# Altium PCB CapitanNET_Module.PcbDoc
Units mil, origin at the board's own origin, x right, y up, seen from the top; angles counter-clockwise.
Board outline not stored, 4 copper layers (Top Layer, Mid-Layer 1, Mid-Layer 2, Bottom Layer); 12 components, 0 nets, 301 pads, 51 vias.
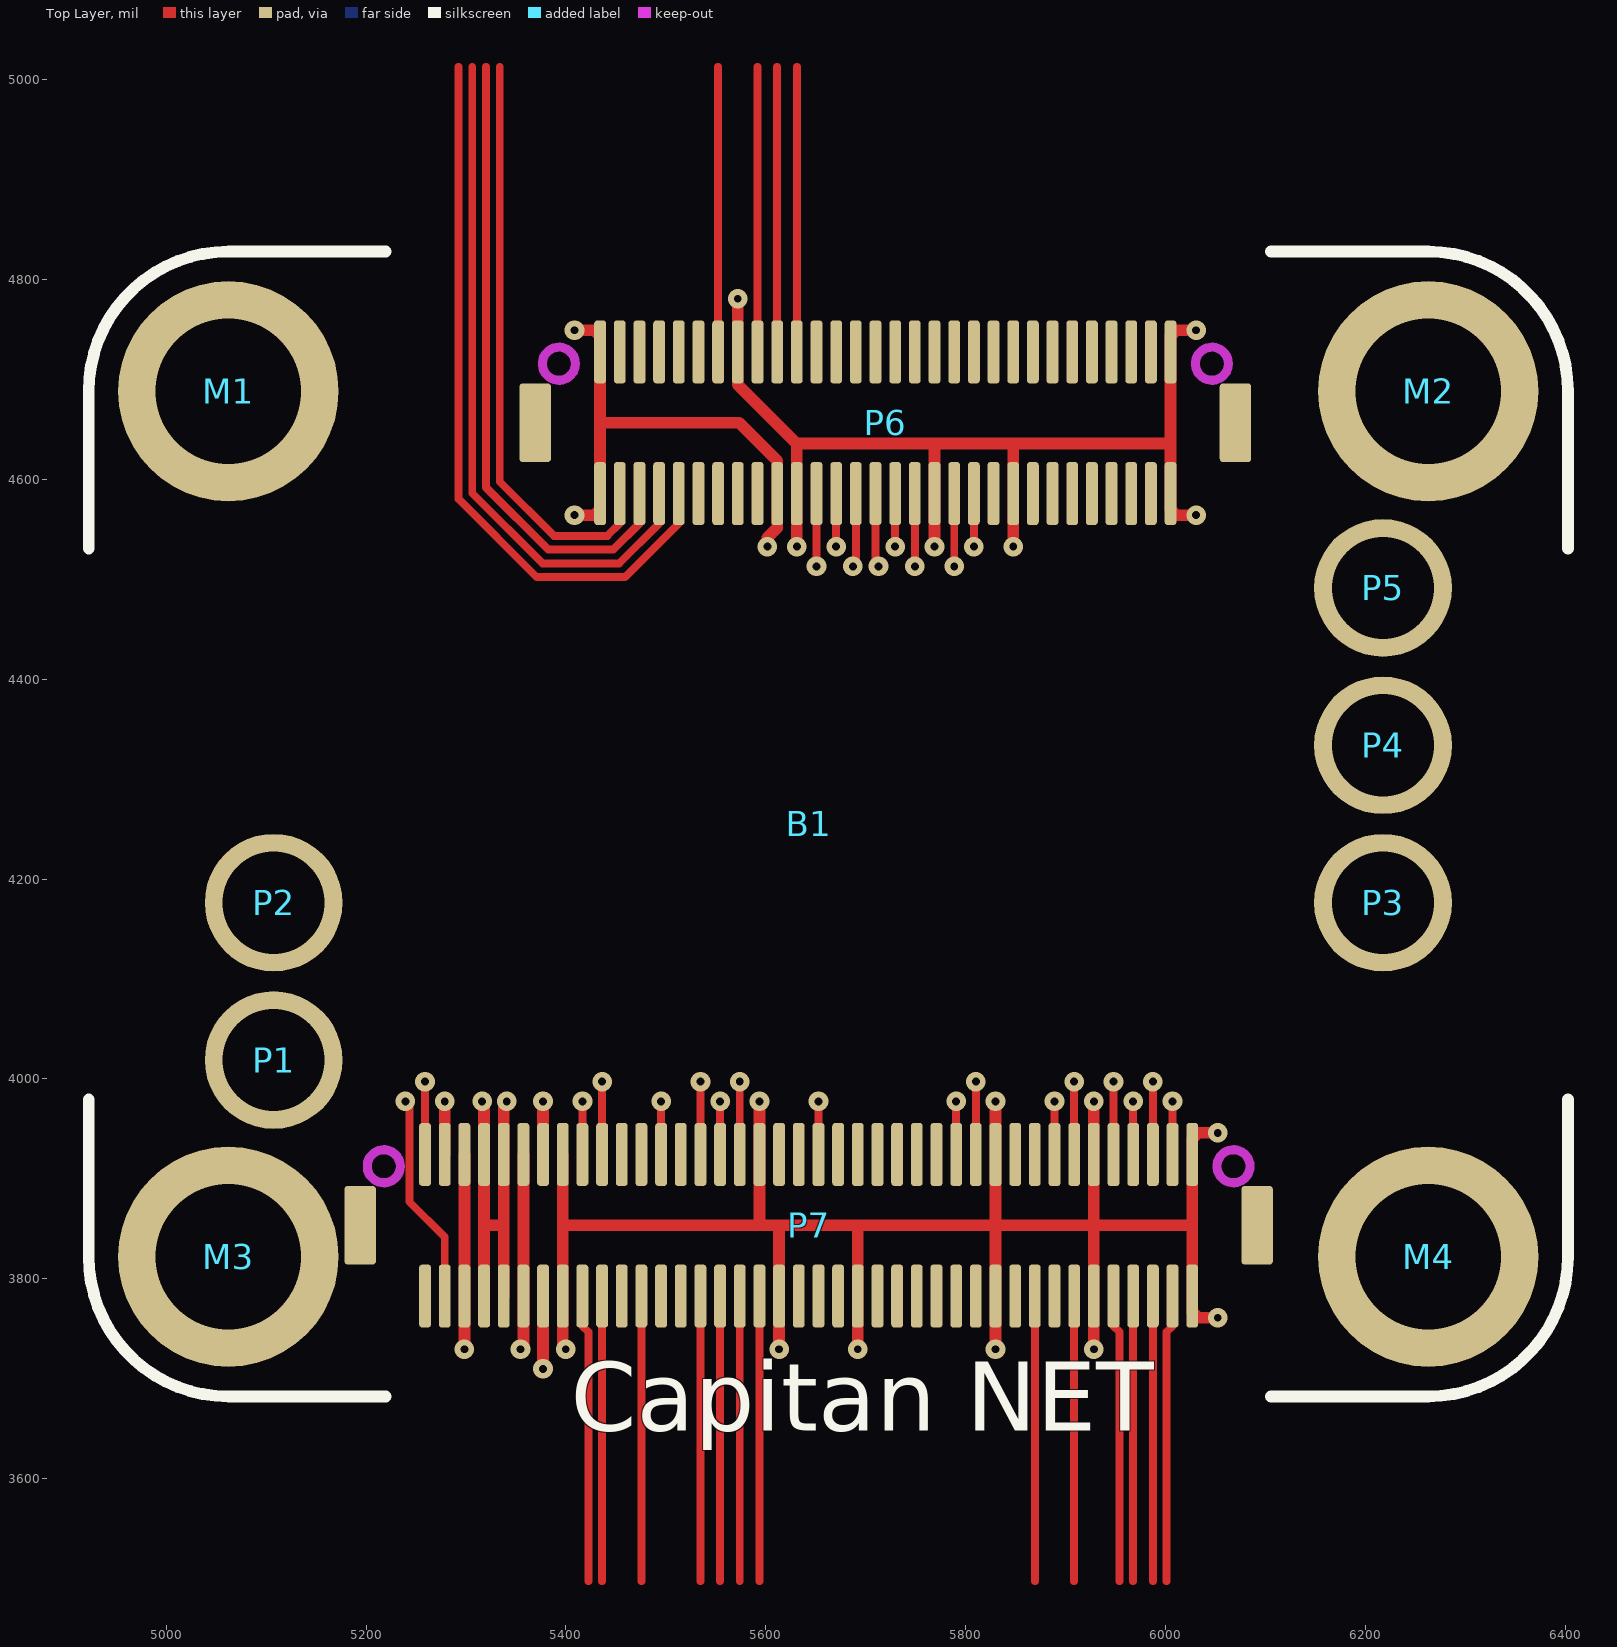
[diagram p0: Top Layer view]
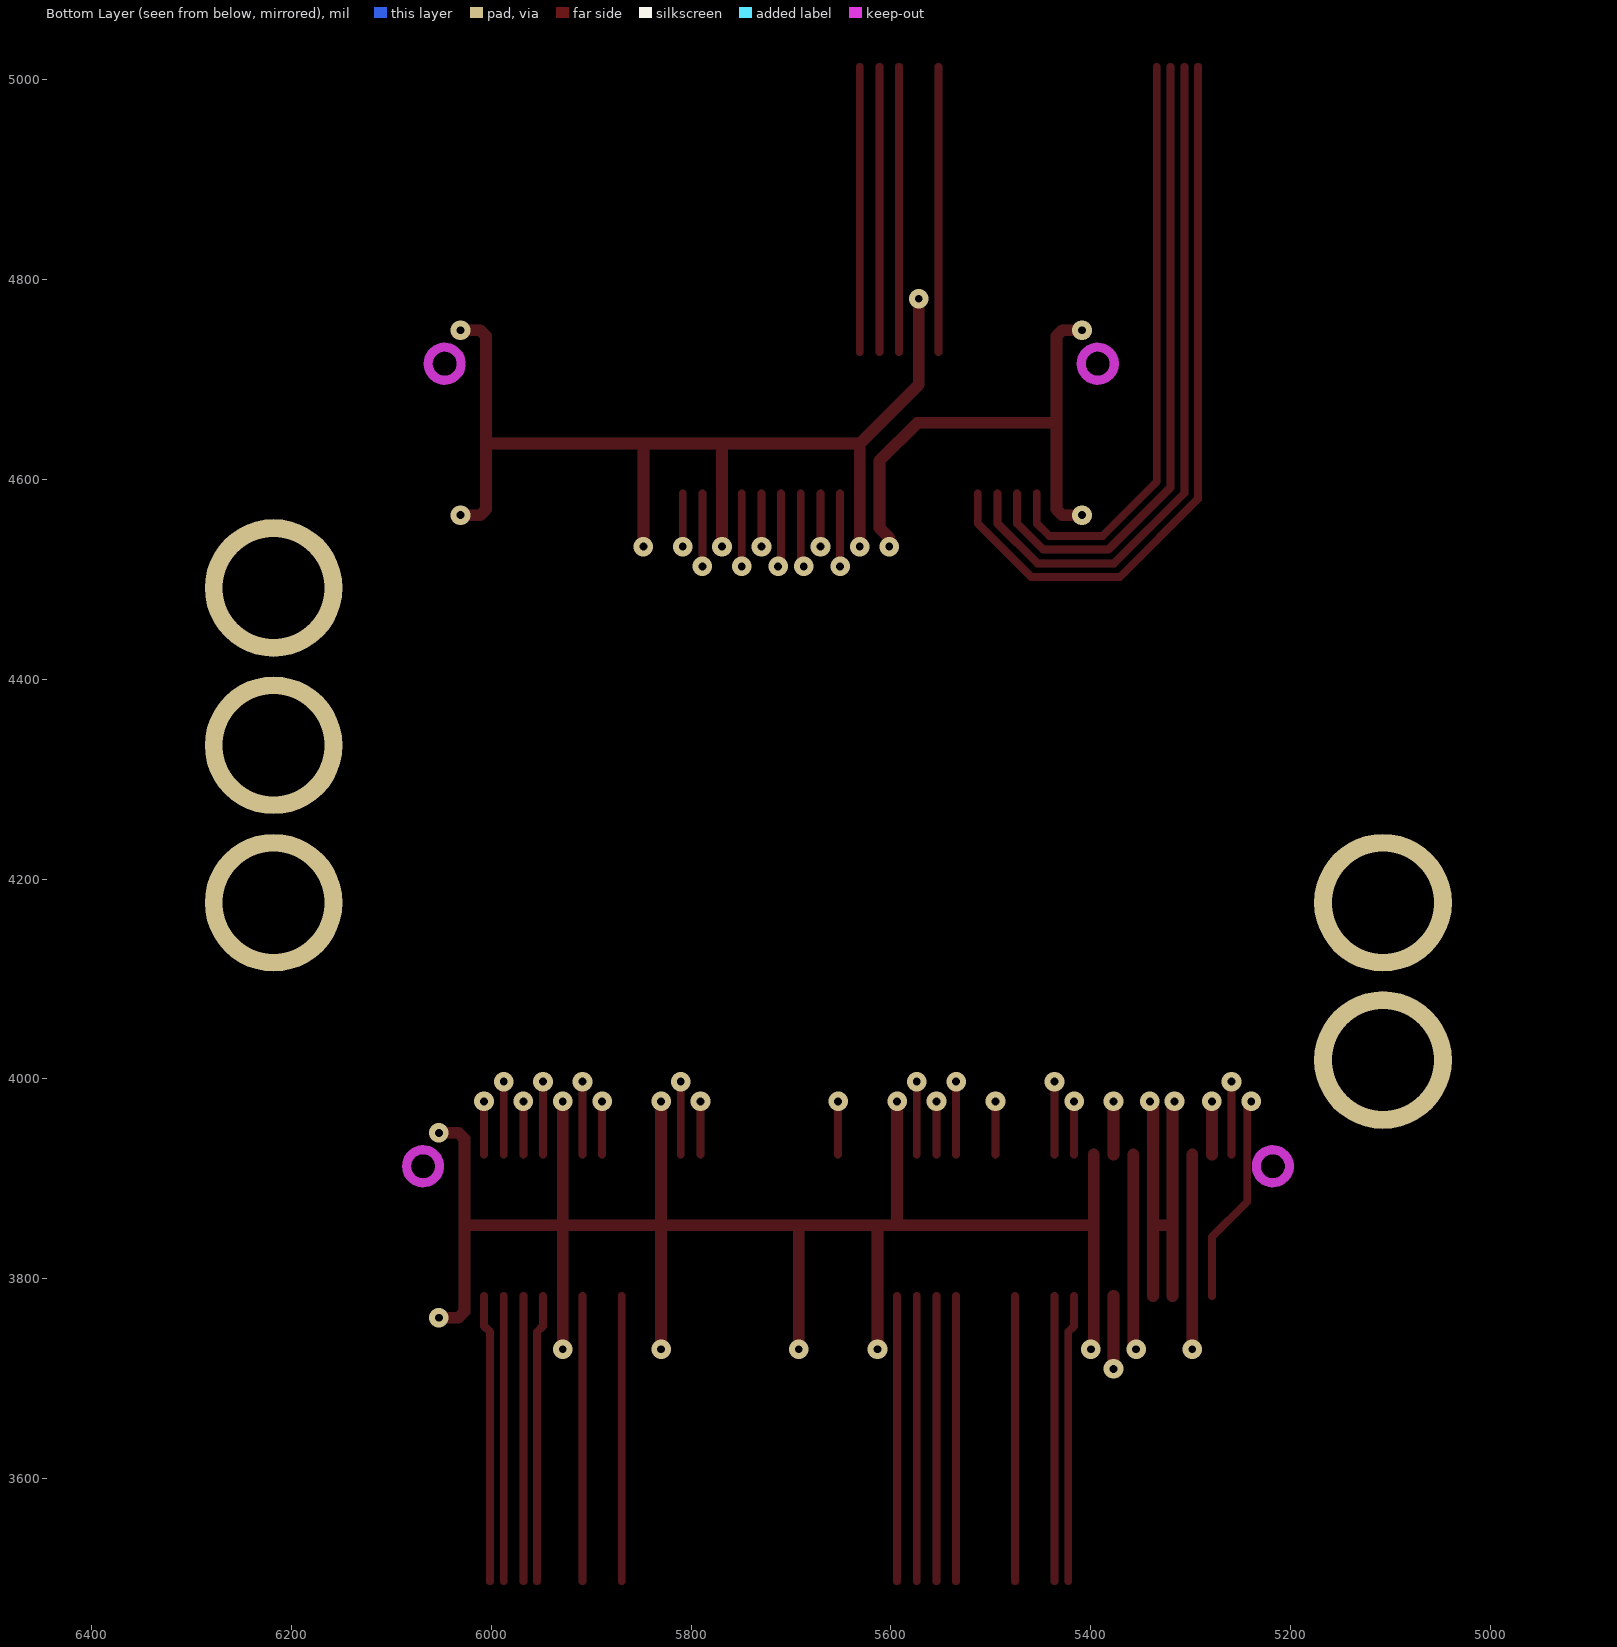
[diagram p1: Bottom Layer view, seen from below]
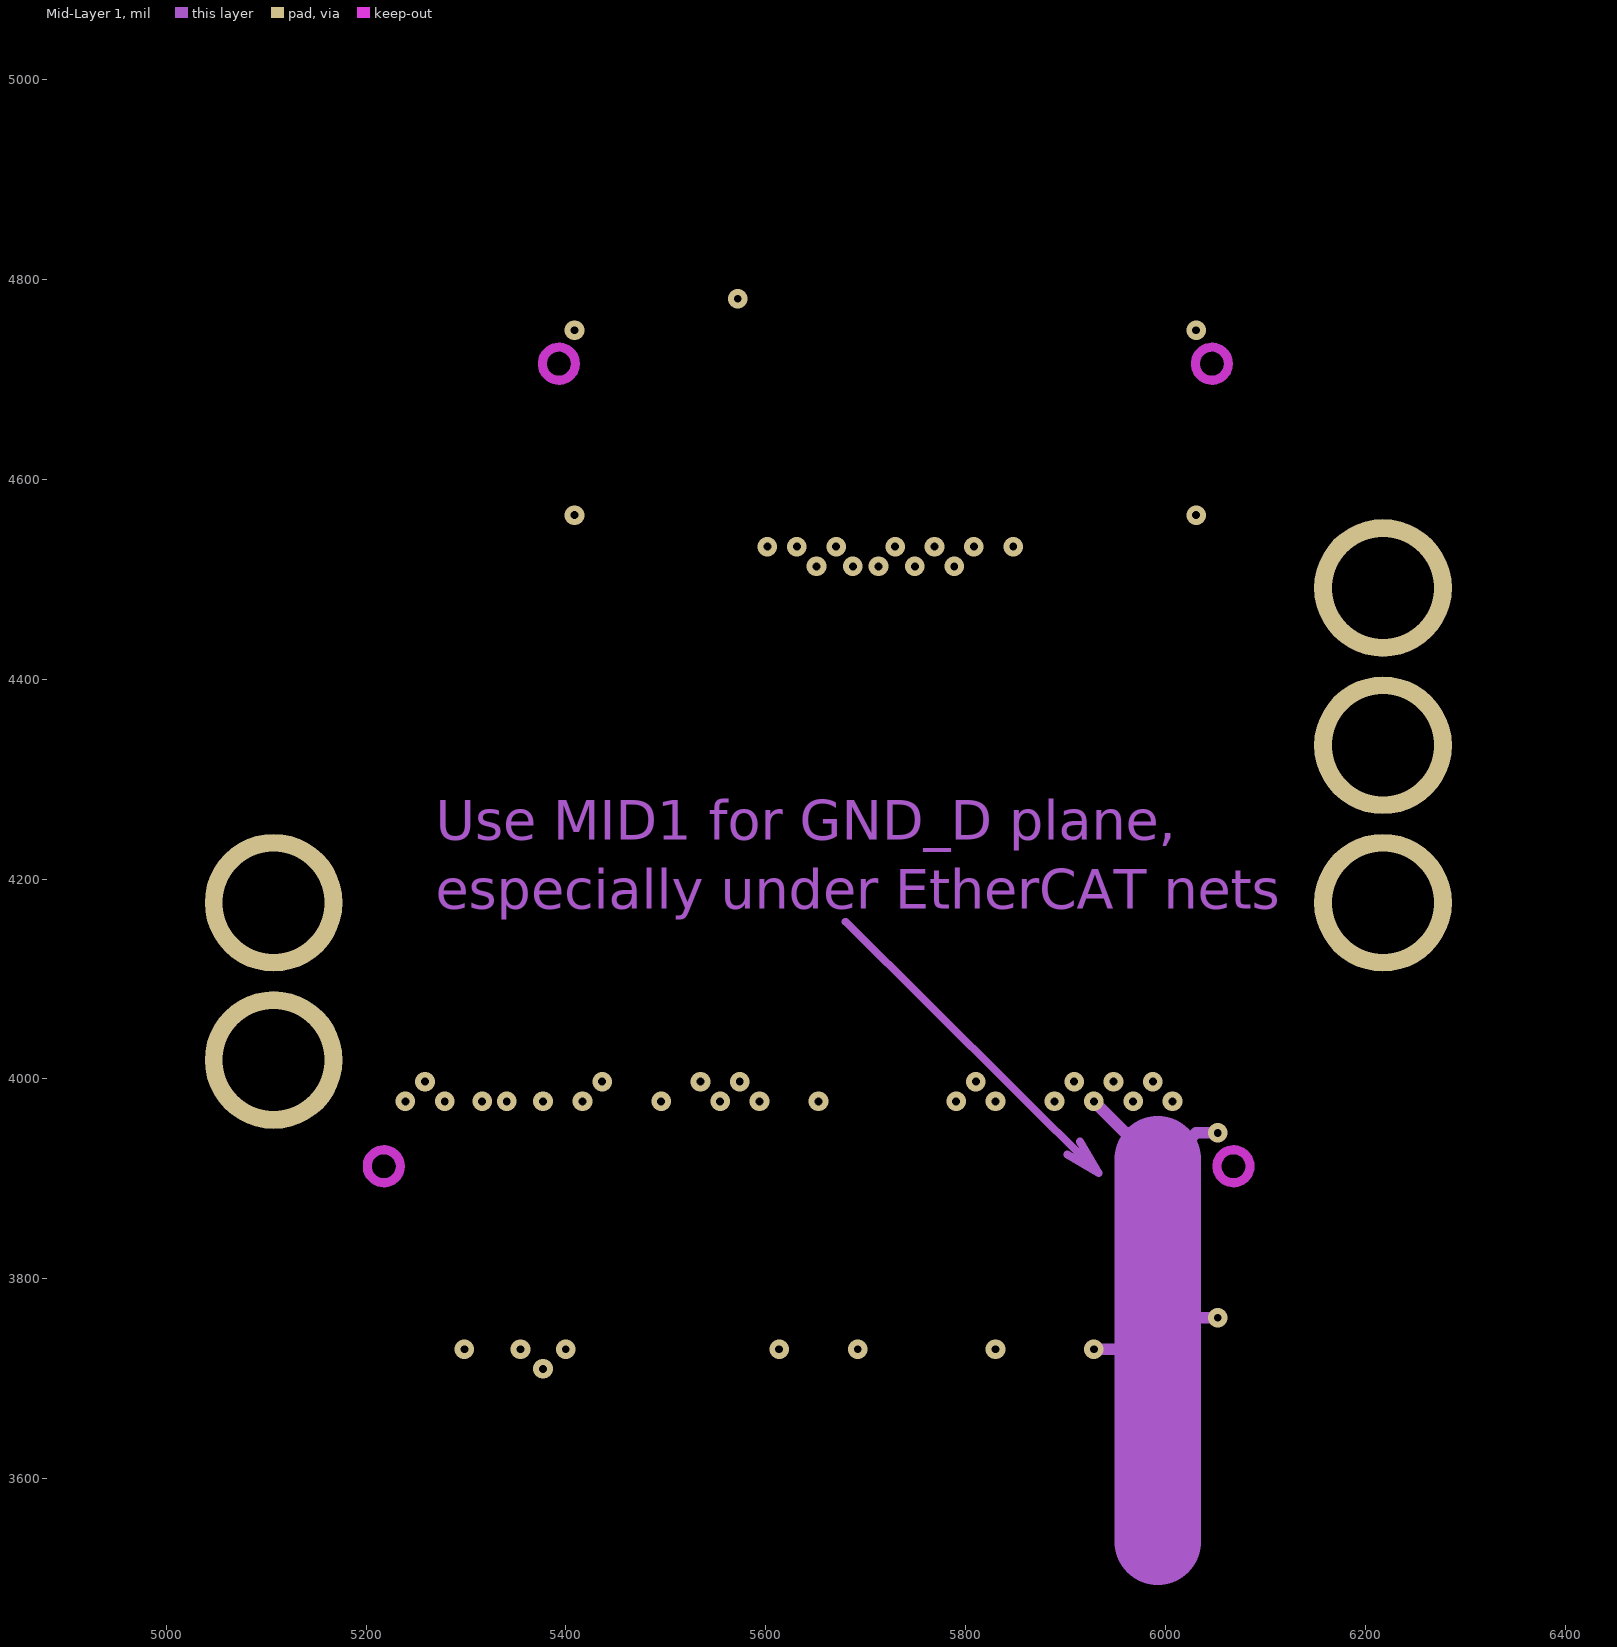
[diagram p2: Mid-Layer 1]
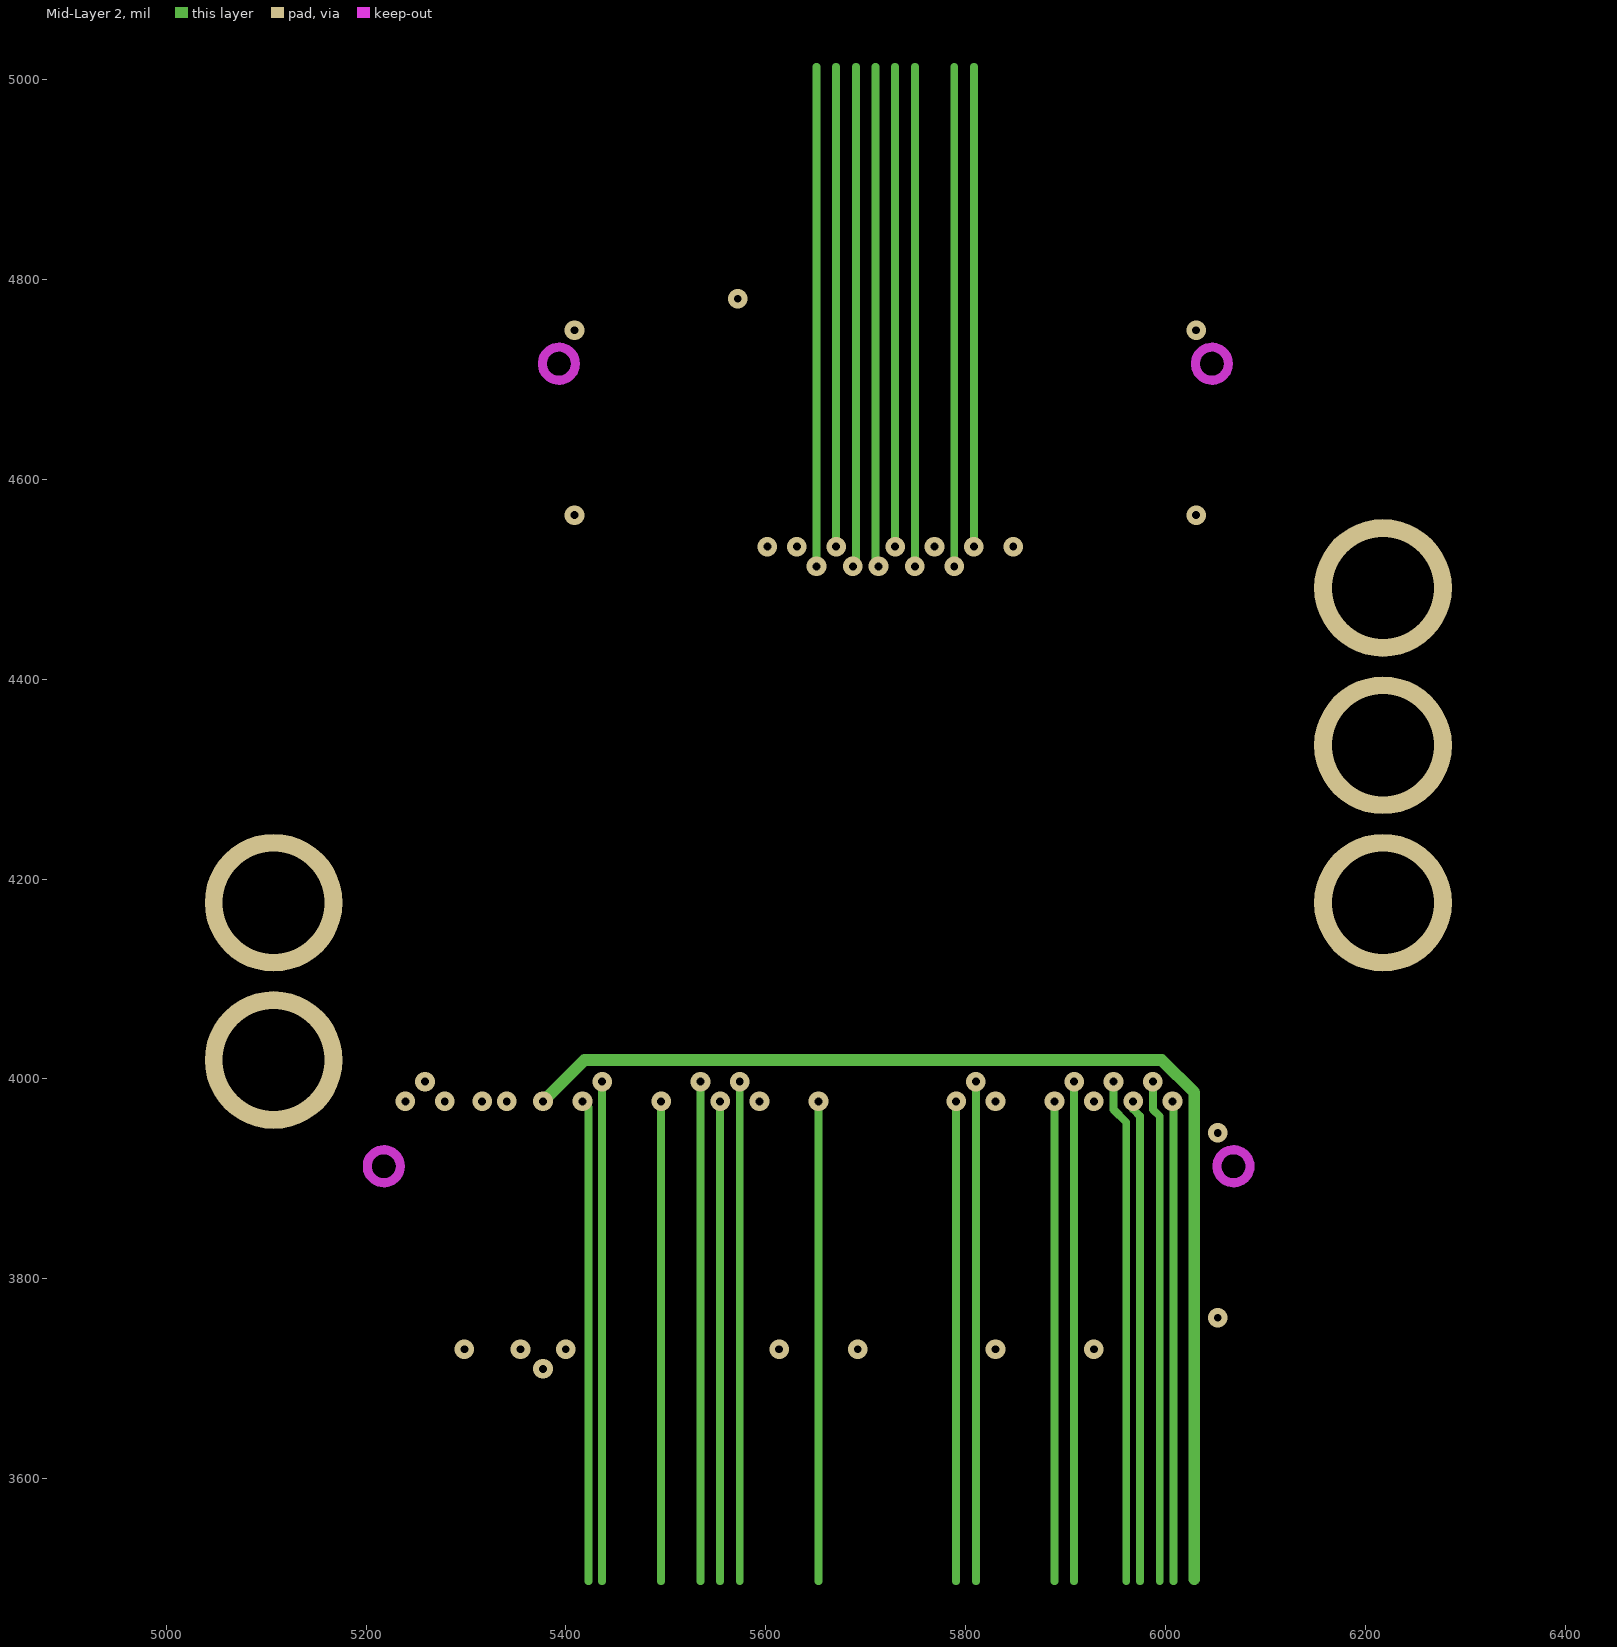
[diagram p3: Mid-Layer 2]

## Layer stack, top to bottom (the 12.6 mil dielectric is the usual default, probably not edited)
Top Solder: solder mask 0.4, Solder Resist, Dk 3.5
Top Layer: signal copper 1.4
Dielectric 1: dielectric 12.6, FR-4, Dk 4.8
Mid-Layer 1: signal copper 1.4
Dielectric2: dielectric 12.6, FR-4, Dk 4.8
Mid-Layer 2: signal copper 1.4
Dielectric3: dielectric 12.6, FR-4, Dk 4.8
Bottom Layer: signal copper 1.4
Bottom Solder: solder mask 0.4, Solder Resist, Dk 3.5

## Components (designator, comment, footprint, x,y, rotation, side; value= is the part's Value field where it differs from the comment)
B1 "Capitan_NET" CAPITAN_NET 5662.6,4255.12 r0 top value=-
M1 "Part Number" WURTH_9774030951R 5062.2,4688.19 r0 top value=-
M2 "Part Number" WURTH_9774030951R 6262.99,4688.19 r0 top value=-
M3 "Part Number" WURTH_9774030951R 5062.2,3822.05 r0 top value=-
M4 "WURTH_9774030951R" WURTH_9774030951R 6262.99,3822.05 r0 top value=-
P1 "Part Number" MillMax_9801-0-15-15-23-27-10-0 5107.48,4018.9 r0 top value=-
P2 "Part Number" MillMax_9801-0-15-15-23-27-10-0 5107.48,4176.38 r0 top value=-
P3 "Part Number" MillMax_9801-0-15-15-23-27-10-0 6217.72,4176.38 r0 top value=-
P4 "Part Number" MillMax_9801-0-15-15-23-27-10-0 6217.72,4333.86 r0 top value=-
P5 "Part Number" MillMax_9801-0-15-15-23-27-10-0 6217.72,4491.34 r0 top value=-
P6 "HIROSE_DF12NB_(3.0)-60DS-0.5V_(51)" HIROSE_DF12NB(3.0)-60DS-0.5V(51) 5719.69,4656.69 r0 top value=-
P7 "HIROSE_DF12NB(3.0)-80DS-0.5V(51)" HIROSE_DF12NB(3.0)-80DS-0.5V(51) 5642.91,3853.54 r0 top value=-

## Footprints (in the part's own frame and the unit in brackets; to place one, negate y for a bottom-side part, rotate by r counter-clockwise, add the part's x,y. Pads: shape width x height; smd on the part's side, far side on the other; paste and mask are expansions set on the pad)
CAPITAN_NET [mm] "Capitan NET 3D model + Pads + Connectors position"
  rrect20% 0.8x2 on Mech5: 0(-11.9,-10.2) 0(-7.45,10.2) 0(10.35,10.2) 0(10.9,-10.2)
  rrect50% 0.3x1.6 on Mech5: 1(-10.25,-8.4) 1(-5.8,12) 2(-10.25,-12) 2(-5.8,8.4) 3(-9.75,-8.4) 3(-5.3,12) 4(-9.75,-12) 4(-5.3,8.4) 5(-9.25,-8.4) 5(-4.8,12) 6(-9.25,-12) 6(-4.8,8.4) 7(-8.75,-8.4) 7(-4.3,12) 8(-8.75,-12) 8(-4.3,8.4) 9(-8.25,-8.4) 9(-3.8,12) 10(-8.25,-12) 10(-3.8,8.4) 11(-7.75,-8.4) 11(-3.3,12) 12(-7.75,-12) 12(-3.3,8.4) 13(-7.25,-8.4) 13(-2.8,12) 14(-7.25,-12) 14(-2.8,8.4) 15(-6.75,-8.4) 15(-2.3,12) 16(-6.75,-12) 16(-2.3,8.4) 17(-6.25,-8.4) 17(-1.8,12) 18(-6.25,-12) 18(-1.8,8.4) 19(-5.75,-8.4) 19(-1.3,12) 20(-5.75,-12) 20(-1.3,8.4) 21(-5.25,-8.4) 21(-0.8,12) 22(-5.25,-12) 22(-0.8,8.4) 23(-4.75,-8.4) 23(-0.3,12) 24(-4.75,-12) 24(-0.3,8.4) 25(-4.25,-8.4) 25(0.2,12) 26(-4.25,-12) 26(0.2,8.4) 27(-3.75,-8.4) 27(0.7,12) 28(-3.75,-12) 28(0.7,8.4) 29(-3.25,-8.4) 29(1.2,12) 30(-3.25,-12) 30(1.2,8.4) 31(-2.75,-8.4) 31(1.7,12) 32(-2.75,-12) 32(1.7,8.4) 33(-2.25,-8.4) 33(2.2,12) 34(-2.25,-12) 34(2.2,8.4) 35(-1.75,-8.4) 35(2.7,12) 36(-1.75,-12) 36(2.7,8.4) 37(-1.25,-8.4) 37(3.2,12) 38(-1.25,-12) 38(3.2,8.4) 39(-0.75,-8.4) 39(3.7,12) 40(-0.75,-12) 40(3.7,8.4) 41(-0.25,-8.4) 41(4.2,12) 42(-0.25,-12) 42(4.2,8.4) 43(0.25,-8.4) 43(4.7,12) 44(0.25,-12) 44(4.7,8.4) 45(0.75,-8.4) 45(5.2,12) 46(0.75,-12) 46(5.2,8.4) 47(1.25,-8.4) 47(5.7,12) 48(1.25,-12) 48(5.7,8.4) 49(1.75,-8.4) 49(6.2,12) 50(1.75,-12) 50(6.2,8.4) 51(2.25,-8.4) 51(6.7,12) 52(2.25,-12) 52(6.7,8.4) 53(2.75,-8.4) 53(7.2,12) 54(2.75,-12) 54(7.2,8.4) 55(3.25,-8.4) 55(7.7,12) 56(3.25,-12) 56(7.7,8.4) 57(3.75,-8.4) 57(8.2,12) 58(3.75,-12) 58(8.2,8.4) 59(4.25,-8.4) 59(8.7,12) 60(4.25,-12) 60(8.7,8.4) 61(4.75,-8.4) 62(4.75,-12) 63(5.25,-8.4) 64(5.25,-12) 65(5.75,-8.4) 66(5.75,-12) 67(6.25,-8.4) 68(6.25,-12) 69(6.75,-8.4) 70(6.75,-12) 71(7.25,-8.4) 72(7.25,-12) 73(7.75,-8.4) 74(7.75,-12) 75(8.25,-8.4) 76(8.25,-12) 77(8.75,-8.4) 78(8.75,-12) 79(9.25,-8.4) 80(9.25,-12)
  silkscreen extent -18.8,-14.55 18.8,14.55, body extent -17.25,-13 17.25,13, height 11
HIROSE_DF12NB(3.0)-60DS-0.5V(51) [mm] "CONN HEADER BLACK 60POS 5MM SMD 0.5MM"
  rrect50% 0.3x1.6 smd: 1(-7.25,1.8) 2(-7.25,-1.8) 3(-6.75,1.8) 4(-6.75,-1.8) 5(-6.25,1.8) 6(-6.25,-1.8) 7(-5.75,1.8) 8(-5.75,-1.8) 9(-5.25,1.8) 10(-5.25,-1.8) 11(-4.75,1.8) 12(-4.75,-1.8) 13(-4.25,1.8) 14(-4.25,-1.8) 15(-3.75,1.8) 16(-3.75,-1.8) 17(-3.25,1.8) 18(-3.25,-1.8) 19(-2.75,1.8) 20(-2.75,-1.8) 21(-2.25,1.8) 22(-2.25,-1.8) 23(-1.75,1.8) 24(-1.75,-1.8) 25(-1.25,1.8) 26(-1.25,-1.8) 27(-0.75,1.8) 28(-0.75,-1.8) 29(-0.25,1.8) 30(-0.25,-1.8) 31(0.25,1.8) 32(0.25,-1.8) 33(0.75,1.8) 34(0.75,-1.8) 35(1.25,1.8) 36(1.25,-1.8) 37(1.75,1.8) 38(1.75,-1.8) 39(2.25,1.8) 40(2.25,-1.8) 41(2.75,1.8) 42(2.75,-1.8) 43(3.25,1.8) 44(3.25,-1.8) 45(3.75,1.8) 46(3.75,-1.8) 47(4.25,1.8) 48(4.25,-1.8) 49(4.75,1.8) 50(4.75,-1.8) 51(5.25,1.8) 52(5.25,-1.8) 53(5.75,1.8) 54(5.75,-1.8) 55(6.25,1.8) 56(6.25,-1.8) 57(6.75,1.8) 58(6.75,-1.8) 59(7.25,1.8) 60(7.25,-1.8)
  round 0 hole 0.6 unplated: H1(-8.3,1.5) H2(8.3,1.5)
  rrect20% 0.8x2 smd: S1(-8.9,0) S2(8.9,0)
  Keep-Out Layer circle w0.23: c-8.3,1.5 r0.42
  Keep-Out Layer circle w0.23: c8.3,1.5 r0.42
  body extent -9.05,-2.3 9.05,2.3, height 2.2
HIROSE_DF12NB(3.0)-80DS-0.5V(51) [mm] "CONN HEADER 80POS 3MM SMD 0.5MM"
  rrect50% 0.3x1.6 smd paste-0.02 mask+0.05: 1(-9.75,1.8) 2(-9.75,-1.8) 3(-9.25,1.8) 4(-9.25,-1.8) 5(-8.75,1.8) 6(-8.75,-1.8) 7(-8.25,1.8) 8(-8.25,-1.8) 9(-7.75,1.8) 10(-7.75,-1.8) 11(-7.25,1.8) 12(-7.25,-1.8) 13(-6.75,1.8) 14(-6.75,-1.8) 15(-6.25,1.8) 16(-6.25,-1.8) 17(-5.75,1.8) 18(-5.75,-1.8) 19(-5.25,1.8) 20(-5.25,-1.8) 21(-4.75,1.8) 22(-4.75,-1.8) 23(-4.25,1.8) 24(-4.25,-1.8) 25(-3.75,1.8) 26(-3.75,-1.8) 27(-3.25,1.8) 28(-3.25,-1.8) 29(-2.75,1.8) 30(-2.75,-1.8) 31(-2.25,1.8) 32(-2.25,-1.8) 33(-1.75,1.8) 34(-1.75,-1.8) 35(-1.25,1.8) 36(-1.25,-1.8) 37(-0.75,1.8) 38(-0.75,-1.8) 39(-0.25,1.8) 40(-0.25,-1.8) 41(0.25,1.8) 42(0.25,-1.8) 43(0.75,1.8) 44(0.75,-1.8) 45(1.25,1.8) 46(1.25,-1.8) 47(1.75,1.8) 48(1.75,-1.8) 49(2.25,1.8) 50(2.25,-1.8) 51(2.75,1.8) 52(2.75,-1.8) 53(3.25,1.8) 54(3.25,-1.8) 55(3.75,1.8) 56(3.75,-1.8) 57(4.25,1.8) 58(4.25,-1.8) 59(4.75,1.8) 60(4.75,-1.8) 61(5.25,1.8) 62(5.25,-1.8) 63(5.75,1.8) 64(5.75,-1.8) 65(6.25,1.8) 66(6.25,-1.8) 67(6.75,1.8) 68(6.75,-1.8) 69(7.25,1.8) 70(7.25,-1.8) 71(7.75,1.8) 72(7.75,-1.8) 73(8.25,1.8) 74(8.25,-1.8) 75(8.75,1.8) 76(8.75,-1.8) 77(9.25,1.8) 78(9.25,-1.8) 79(9.75,1.8) 80(9.75,-1.8)
  round 0 hole 0.6 unplated: H1(-10.8,1.5) H2(10.8,1.5)
  rrect20% 0.8x2 smd: S1(-11.4,0) S2(11.4,0)
  Keep-Out Layer circle w0.23: c-10.8,1.5 r0.42
  Keep-Out Layer circle w0.23: c10.8,1.5 r0.42
  body extent -11.55,-2.3 11.55,2.3, height 2.2
MillMax_9801-0-15-15-23-27-10-0 [mm]
  round 3.5 hole 2.6: 1(0,0)
  body extent -1.52,-1.52 1.52,1.52, height 1.78
WURTH_9774030951R [mm] "M2.5 SPACER Thread Internal, Length 3mm"
  round 5.6 / inner round 0 / far side round 0 hole 3.7 unplated paste-403.566: 1(0,0)
  body extent -2.55,-2.55 2.55,2.55, height 3.01

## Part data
B1: "Capitan NET high-performance Servo Drive from Ingenia Motion Control.", AlternativeManufacturer=Ingenia, ManufacturerPN=CAP-NET-E, Package Type=-, TemperatureMaxC=85, TemperatureMinC=-40
M1 M2 M3 M4: library part SPACER_SMD_ROUND_M2.5x3mm_NO_THREAD, "Round SMD standoff M2.5 3mm height No Threaded Steel", ManufacturerName="Wurth Electronics Inc", ManufacturerPN=9774030951R, Package Name="SPACER M2.5 SMD REEL 3MM", Package Type=SM, Supplier Part Number 1=732-7086-1-ND, TemperatureMaxC=200, TemperatureMinC=-40
P1 P2 P3 P4 P5: library part MillMax_9801-0-15-15-23-27-10-0, "1pin, receptacle for MillMax 6142, blind end", ManufacturerName=MillMax, ManufacturerPN=9801-0-15-15-23-27-10-0, Package Type=TH, Supplier Part Number 1=ED1006-ND, TemperatureMaxC=125, TemperatureMinC=-55
P6: "Connector SMD Mezzanine, Black 60 ways, 0.5mm pitch, 3mm stack height. Male", ManufacturerName=Hirose, ManufacturerPN=DF12NB(3.0)-60DS-0.5V(51), Package Name="SMD connector 60 ways male", Package Type=SM, Supplier Part Number 1=26-DF12NB(3.0)-60DS-0.5V(51)CT, TemperatureMaxC=125, TemperatureMinC=-55
P7: "Connector SMD Mezzanine, 80 ways, 0.5mm pitch, 3mm stack height. Male with metal fitting", AlternativeManufacturer=Hirose, ManufacturerPN=DF12NB(3.0)-80DS-0.5V(51), Package Name="SMD connector 80 ways male", Package Type=SM, Supplier Part Number 1=26-DF12NB(3.0)-80DS-0.5V(51), TemperatureMaxC=125, TemperatureMinC=-45

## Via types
v1: diameter 19.68, hole 7.87, Top Layer to Bottom Layer, 51 vias

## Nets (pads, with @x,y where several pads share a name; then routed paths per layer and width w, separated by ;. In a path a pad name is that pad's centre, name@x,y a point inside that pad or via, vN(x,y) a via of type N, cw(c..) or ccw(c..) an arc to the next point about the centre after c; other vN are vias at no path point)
pads on no net: B1.0 B1.1 B1.2 B1.3 B1.4 B1.5 B1.6 B1.7 B1.8 B1.9 B1.10 B1.11 B1.12 B1.13 B1.14 B1.15 B1.16 B1.17 B1.18 B1.19 B1.20 B1.21 B1.22 B1.23 B1.24 B1.25 B1.26 B1.27 B1.28 B1.29 B1.30 B1.31 B1.32 B1.33 B1.34 B1.35 B1.36 B1.37 B1.38 B1.39 B1.40 B1.41 B1.42 B1.43 B1.44 B1.45 B1.46 B1.47 B1.48 B1.49 B1.50 B1.51 B1.52 B1.53 B1.54 B1.55 B1.56 B1.57 B1.58 B1.59 B1.60 B1.61 B1.62 B1.63 B1.64 B1.65 B1.66 B1.67 B1.68 B1.69 B1.70 B1.71 B1.72 B1.73 B1.74 B1.75 B1.76 B1.77 B1.78 B1.79 B1.80 M1.1 M2.1 M3.1 M4.1 P1.1 P2.1 P3.1 P4.1 P5.1 P6.1 P6.2 P6.3 P6.4 P6.5 P6.6 P6.7 P6.8 P6.9 P6.10 P6.11 P6.12 P6.13 P6.14 P6.15 P6.16 P6.17 P6.18 P6.19 P6.20 P6.21 P6.22 P6.23 P6.24 P6.25 P6.26 P6.27 P6.28 P6.29 P6.30 P6.31 P6.32 P6.33 P6.34 P6.35 P6.36 P6.37 P6.38 P6.39 P6.40 P6.41 P6.42 P6.43 P6.44 P6.45 P6.46 P6.47 P6.48 P6.49 P6.50 P6.51 P6.52 P6.53 P6.54 P6.55 P6.56 P6.57 P6.58 P6.59 P6.60 P6.H1 P6.H2 P6.S1 P6.S2 P7.1 P7.2 P7.3 P7.4 P7.5 P7.6 P7.7 P7.8 P7.9 P7.10 P7.11 P7.12 P7.13 P7.14 P7.15 P7.16 P7.17 P7.18 P7.19 P7.20 P7.21 P7.22 P7.23 P7.24 P7.25 P7.26 P7.27 P7.28 P7.29 P7.30 P7.31 P7.32 P7.33 P7.34 P7.35 P7.36 P7.37 P7.38 P7.39 P7.40 P7.41 P7.42 P7.43 P7.44 P7.45 P7.46 P7.47 P7.48 P7.49 P7.50 P7.51 P7.52 P7.53 P7.54 P7.55 P7.56 P7.57 P7.58 P7.59 P7.60 P7.61 P7.62 P7.63 P7.64 P7.65 P7.66 P7.67 P7.68 P7.69 P7.70 P7.71 P7.72 P7.73 P7.74 P7.75 P7.76 P7.77 P7.78 P7.79 P7.80 P7.H1 P7.H2 P7.S1 P7.S2
copper on no net: | length 27341.9
  Top Layer w7.87: v1(5239.37,3977.56) 5243.31,3973.62 5243.31,3877.17 5278.74,3841.73 5278.74,3782.68 ; 5259.06,3924.41 v1(5259.06,3997.24) ; 5292.52,5012.99 5292.52,4580.52 5370.87,4502.17 5459.24,4502.17 5512.99,4555.92 5512.99,4585.83 ; 5306.3,5012.99 5306.3,4586.22 5376.58,4515.94 5453.33,4515.94 5493.31,4555.92 5493.31,4585.83 ; 5320.08,5012.99 5320.08,4591.93 5382.28,4529.72 5447.43,4529.72 5473.62,4555.92 5473.62,4585.83 ; 5333.86,5012.99 5333.86,4597.64 5387.99,4543.5 5441.52,4543.5 5453.94,4555.92 5453.94,4585.83 ; 5416.54,3782.68 5416.54,3752.77 5422.44,3746.87 5422.44,3497.24 ; 5416.54,3924.41 v1(5416.54,3977.56) ; 5436.22,3497.24 5436.22,3782.68 ; 5436.22,3924.41 v1(5436.22,3997.24) ; 5475.59,3497.24 5475.59,3782.68 ; 5495.28,3924.41 v1(5495.28,3977.56) ; 5534.65,3497.24 5534.65,3782.68 ; 5534.65,3924.41 v1(5534.65,3997.24) ; 5552.36,4727.56 5552.36,5012.99 ; 5554.33,3497.24 5554.33,3782.68 ; 5554.33,3924.41 v1(5554.33,3977.56) ; 5574.02,3497.24 5574.02,3782.68 ; 5574.02,3924.41 v1(5574.02,3997.24) ; 5591.73,4727.56 5591.73,5012.99 ; 5593.7,3497.24 5593.7,3782.68 ; 5611.42,4727.56 5611.42,5012.99 ; 5631.1,4727.56 5631.1,5012.99 ; v1(5650.79,4512.99) 5650.79,4585.83 ; 5652.76,3924.41 v1(5652.76,3977.56) ; v1(5670.47,4532.68) 5670.47,4585.83 ; v1(5687.2,4512.99) 5690.16,4515.95 5690.16,4585.83 ; 5709.84,4585.83 5709.84,4515.95 v1(5712.8,4512.99) ; v1(5729.53,4532.68) 5729.53,4585.83 ; v1(5749.21,4512.99) 5749.21,4585.83 ; v1(5788.58,4512.99) 5788.58,4585.83 ; 5790.55,3924.41 v1(5790.55,3977.56) ; v1(5808.27,4532.68) 5808.27,4585.83 ; 5810.24,3924.41 v1(5810.24,3997.24) ; 5869.29,3497.24 5869.29,3782.68 ; 5888.98,3924.41 v1(5888.98,3977.56) ; 5908.66,3497.24 5908.66,3782.68 ; 5908.66,3924.41 v1(5908.66,3997.24) ; 5948.03,3782.68 5948.03,3752.77 5953.94,3746.87 5953.94,3497.24 ; 5948.03,3924.41 v1(5948.03,3997.24) ; 5967.72,3497.24 5967.72,3782.68 ; 5967.72,3924.41 v1(5967.72,3977.56) ; 5987.4,3497.24 5987.4,3782.68 ; 5987.4,3924.41 v1(5987.4,3997.24) ; 6001.18,3497.24 6001.18,3746.87 6007.09,3752.77 6007.09,3782.68 ; 6007.09,3924.41 v1(6007.09,3977.56)
  Top Layer w11.81: 5278.74,3924.41 v1(5278.74,3977.56) ; v1(5298.43,3729.53) 5298.43,3924.41 ; 5318.11,3782.68 5318.11,3853.54 ; v1@5318.11,3977.56 5318.11,3924.41 5318.11,3853.54 ; 5337.8,3782.68 5337.8,3853.54 ; v1@5337.8,3977.56 5337.8,3924.41 5337.8,3853.54 ; v1(5354.53,3729.53) 5354.53,3731.66 5357.48,3734.61 5357.48,3782.68 5357.48,3924.41 ; v1(5377.17,3709.84) 5377.17,3782.68 ; 5377.17,3924.41 v1(5377.17,3977.56) ; 5396.85,3924.41 5396.85,3853.54 ; v1(5399.8,3729.53) 5399.8,3731.66 5396.85,3734.61 5396.85,3782.68 5396.85,3853.54 ; v1(5408.66,4564.17) 5428.35,4564.17 5434.25,4570.08 5434.25,4585.83 5434.25,4656.69 ; v1(5408.66,4749.21) 5428.35,4749.21 5434.25,4743.31 5434.25,4727.56 5434.25,4656.69 ; v1(5572.05,4780.71) 5572.05,4727.56 5572.05,4694.87 5631.1,4635.81 ; v1(5593.7,3977.56) 5593.7,3853.54 ; v1(5601.57,4532.68) 5601.57,4541.54 5611.42,4551.38 5611.42,4585.83 5611.42,4618.52 5573.24,4656.69 5434.25,4656.69 ; v1(5613.39,3729.53) 5613.39,3853.54 ; v1(5631.1,4532.68) 5631.1,4585.83 5631.1,4635.81 ; v1(5692.13,3729.53) 5692.13,3853.54 ; v1(5768.9,4532.68) 5768.9,4585.83 5768.9,4635.81 ; v1(5829.92,3729.53) 5829.92,3853.54 ; 5829.92,3855.51 v1(5829.92,3977.56) ; v1(5847.64,4532.68) 5847.64,4585.83 5847.64,4635.81 ; v1(5928.35,3729.53) 5928.35,3853.54 ; v1(5928.35,3977.56) 5928.35,3853.54 ; v1(6030.71,4564.17) 6011.02,4564.17 6005.12,4570.08 6005.12,4585.83 6005.12,4635.81 ; v1(6030.71,4749.21) 6011.02,4749.21 6005.12,4743.31 6005.12,4727.56 6005.12,4635.81 ; v1(6052.36,3761.02) 6032.68,3761.02 6026.77,3766.93 6026.77,3853.54 ; v1(6052.36,3946.06) 6032.68,3946.06 6026.77,3940.16 6026.77,3853.54 ; 5318.11,3853.54 5337.8,3853.54 ; 5396.85,3853.54 5593.7,3853.54 ; 5593.7,3853.54 5613.39,3853.54 ; 5613.39,3853.54 5692.13,3853.54 ; 5631.1,4635.81 5768.9,4635.81 ; 5692.13,3853.54 5829.92,3853.54 ; 5768.9,4635.81 5847.64,4635.81 ; 5829.92,3853.54 5928.35,3853.54 ; 5847.64,4635.81 6005.12,4635.81 ; 5928.35,3853.54 6026.77,3853.54
  Mid-Layer 1 w7.87: 5679.93,4157.27 5933.27,3905.71 ; 5901.77,3924.41 5933.27,3905.71 ; 5914.57,3937.2 5933.27,3905.71
  Mid-Layer 1 w11.81: v1(5928.35,3729.53) 5955.91,3729.53 5987.4,3761.02 5992.32,3761.02 v1(6052.36,3761.02) ; v1(5928.35,3977.56) 5959.84,3946.06 5982.97,3946.06 6006.84,3922.2 6030.71,3946.06 v1(6052.36,3946.06)
  Mid-Layer 1 w86.61: 5992.32,3536.61 5992.32,3755.12 ; 5992.32,3744.29 5992.32,3761.02 5992.32,3919.49
  Mid-Layer 2 w7.87: v1(5416.54,3977.56) 5422.44,3971.65 5422.44,3497.24 ; 5436.22,3497.24 v1(5436.22,3997.24) ; 5495.28,3497.24 v1(5495.28,3977.56) ; 5534.65,3497.24 v1(5534.65,3997.24) ; 5554.33,3497.24 v1(5554.33,3977.56) ; 5574.02,3497.24 v1(5574.02,3997.24) ; v1(5650.79,4512.99) 5650.79,5012.99 ; 5652.76,3497.24 v1(5652.76,3977.56) ; v1(5670.47,4532.68) 5670.47,5012.99 ; v1(5687.2,4512.99) 5690.16,4515.95 5690.16,5012.99 ; 5709.84,5012.99 5709.84,4515.95 v1(5712.8,4512.99) ; v1(5729.53,4532.68) 5729.53,5012.99 ; v1(5749.21,4512.99) 5749.21,5012.99 ; v1(5788.58,4512.99) 5788.58,5012.99 ; 5790.55,3497.24 v1(5790.55,3977.56) ; v1(5808.27,4532.68) 5808.27,5012.99 ; 5810.24,3497.24 v1(5810.24,3997.24) ; 5888.98,3497.24 v1(5888.98,3977.56) ; 5908.66,3497.24 v1(5908.66,3997.24) ; v1(5948.03,3997.24) 5948.03,3969.41 5960.83,3956.61 5960.83,3497.24 ; v1(5967.72,3977.56) 5967.72,3969.6 5974.61,3962.71 5974.61,3497.24 ; v1(5987.4,3997.24) 5987.4,3969.41 5994.29,3962.52 5994.29,3497.24 ; v1@6007.09,3974.36 v1(6007.09,3977.56) ; 6008.07,3497.24 v1@6008.07,3968.46
  Mid-Layer 2 w11.81: v1(5377.17,3977.56) 5418.5,4018.9 5996.37,4018.9 6028.74,3986.53 6028.74,3499.21
  other v1: 5316.14,3977.56 5340.75,3977.56

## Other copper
Mid-Layer 1:
  text "Use MID1 for GND_D plane," at 5269.88,4239.37 h39.37
  text "especially under EtherCAT nets" at 5269.88,4170.47 h39.37

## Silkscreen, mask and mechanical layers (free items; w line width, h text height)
Mechanical 15:
  circle w7.87: c5217.72,3912.6 r16.54
  circle w7.87: c5392.91,4715.75 r16.54
  circle w7.87: c6068.11,3912.6 r16.54
  circle w7.87: c6046.46,4715.75 r16.54
  text "← Holes for back compatibility →" at 5410.57,4727.44 h47.24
